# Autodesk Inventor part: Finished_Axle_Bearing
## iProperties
Created: 2004-07
Part Number: Finished_Axle_Bearing
Document SubType Name: Modeling
Designer: rak
Manufacturer: Standard
Standards Organization: Custom
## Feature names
1. Extrusion1
2. Extrusion2
3. Revolution1
